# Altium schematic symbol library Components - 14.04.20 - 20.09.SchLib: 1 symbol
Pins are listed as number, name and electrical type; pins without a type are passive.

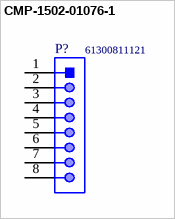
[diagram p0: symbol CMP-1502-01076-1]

## CMP-1502-01076-1
designator P?, comment 61300811121
THT Vertical Pin Header WR-PHD, Pitch 2.54 mm, Single Row, 8 pins; Manufacturer: Wurth Elektronik; Rated Current: 3A; Pin Number: 8; Working Voltage: 250VAC; Gender: Male; Contact Resistance: 20mOhm; Pitch: 2.54mm; Withstanding Voltage: 500VAC
footprint 61300811121 (Pin Header, pitch 2.54 mm, THT, Vertical, single row, 8p)
pins: 1, 2, 3, 4, 5, 6, 7, 8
